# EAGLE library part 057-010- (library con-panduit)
CONNECTOR 10-pin series 057 contact pc board low profile headers
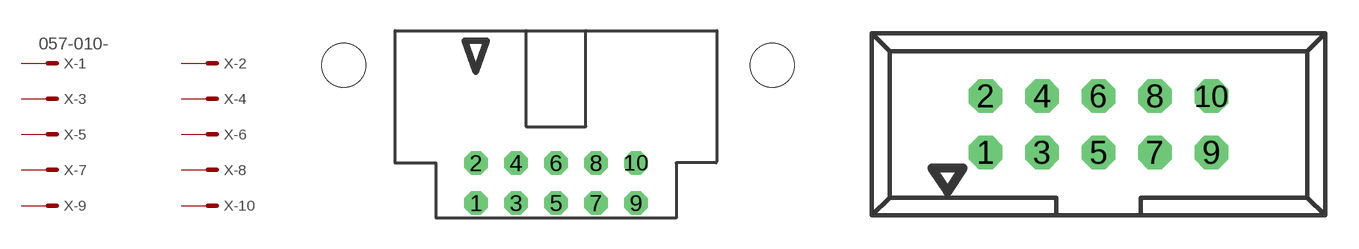
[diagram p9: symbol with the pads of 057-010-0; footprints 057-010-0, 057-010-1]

Designator prefix X; gates -1=MV -2=M -3=M -4=M -5=M -6=M -7=M -8=M -9=M -10=M

## 057-010-0 (OC_FARNELL: unknown; OC_NEWARK: unknown)  [057-010-0]
1  -1:S  pas
2  -2:S  pas
3  -3:S  pas
4  -4:S  pas
5  -5:S  pas
6  -6:S  pas
7  -7:S  pas
8  -8:S  pas
9  -9:S  pas
10  -10:S  pas

## 057-010-1 (OC_FARNELL: unknown; OC_NEWARK: unknown)  [057-010-1]
Pads as for 057-010-0

## Footprint 057-010-0 (pad centres in mm)
CONNECTOR series 057 contact pc board low profile headers angled
drill 1 octagon: 1 -5.08,-5.08; 2 -5.08,-2.54; 3 -2.54,-5.08; 4 -2.54,-2.54; 5 0,-5.08; 6 0,-2.54; 7 2.54,-5.08; 8 2.54,-2.54; 9 5.08,-5.08; 10 5.08,-2.54
hole 2.8 at -13.48,3.66
hole 2.8 at 13.73,3.66

## Footprint 057-010-1 (pad centres in mm)
CONNECTOR series 057 contact pc board low profile headers straight
drill 1 octagon: 1 -5.08,-1.27; 2 -5.08,1.27; 3 -2.54,-1.27; 4 -2.54,1.27; 5 0,-1.27; 6 0,1.27; 7 2.54,-1.27; 8 2.54,1.27; 9 5.08,-1.27; 10 5.08,1.27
